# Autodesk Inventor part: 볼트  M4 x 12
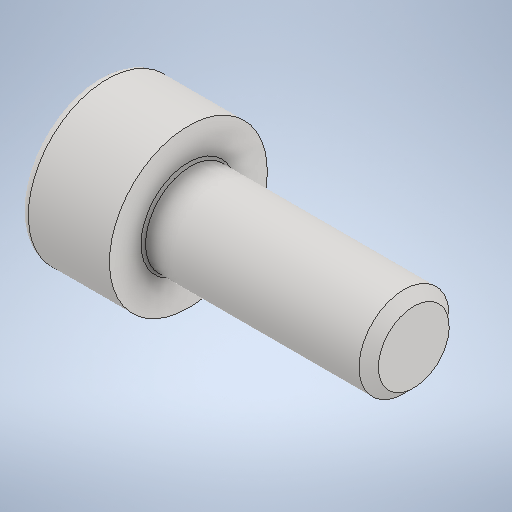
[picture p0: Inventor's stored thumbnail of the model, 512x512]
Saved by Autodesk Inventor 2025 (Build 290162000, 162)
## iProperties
Created: 2024-08
Part Number: 볼트  M4 x 12
Material: 스테인리스강
Description: 6각머리 태핑 나사
Document SubType Name: Modeling
Designer: onair
Density: 8.08 g/cm^3
Appearance: 기본값
Author: jhkim
Sending System: Autodesk Inventor 2025
Preprocessor: ST-DEVELOPER v20
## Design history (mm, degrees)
feature "Solid1"
node "솔리드1"
